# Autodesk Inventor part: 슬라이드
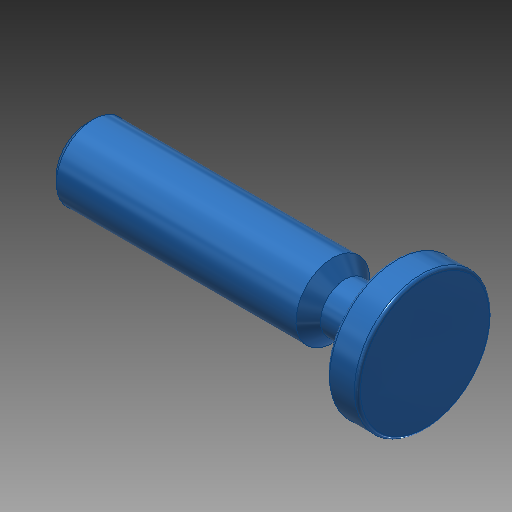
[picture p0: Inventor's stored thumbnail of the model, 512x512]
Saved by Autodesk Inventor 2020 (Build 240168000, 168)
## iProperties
Created: 2015-12
Part Number: 슬라이드
Document SubType Name: Modeling
Designer: mdu
Density: 7.86 g/cm^3
Mass: 54.7221 g
Surface Area: 29.08 cm^2
Volume: 6.9621 cm^3
Material: 강철, 연강
Appearance: 청록색
Company: 한국ATC센터
Author: mdu
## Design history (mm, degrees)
sketch "스케치1"
  geometry: L1 (-27.5, 0)-(27.5, 0); L2 (27.5, 0)-(27.5, 11); L3 (27.5, 11)-(22.5, 11); L4 (22.5, 11)-(22.5, 4); L5 (22.5, 4)-(14.5, 4); L6 (14.5, 4)-(12.5, 6); L7 (12.5, 6)-(-27.5, 6); L8 (-27.5, 6)-(-27.5, 0); 1 further point
  constraints: 16 end point, 4 parallel, 2 midpoint, 2 perpendicular, 1 horizontal
  dimensions: "d0" = 55 distance of L1.start L1.end; "d1" = 12 diameter of L7 L1; "d2" = 22 diameter of L3 L1; "d3" = 5 distance of L2.end L3.end; "d4" = 8 diameter of L5 L1; "d5" = 135 deg angle of L6 L5; "d6" = 15 distance from line of L2 L6.end
revolve "회전1" sketch "스케치1" stored, may be unused: angle "d7" = 90 deg
chamfer "모따기1" distance "d8" = 1; stored, may be unused: second distance "d9" = 2, angle "d10" = 45 deg
fillet "모깎기1" dims "d11" = 0.5
node "솔리드1"
